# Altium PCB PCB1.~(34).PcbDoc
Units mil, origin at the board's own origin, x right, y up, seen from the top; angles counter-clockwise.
Board outline 2677.17 x 2677.17 mil, 2 copper layers (Top Layer, Bottom Layer); 27 components, 21 nets, 95 pads, 0 vias.
Unrouted connection lines stored in the file: 51.
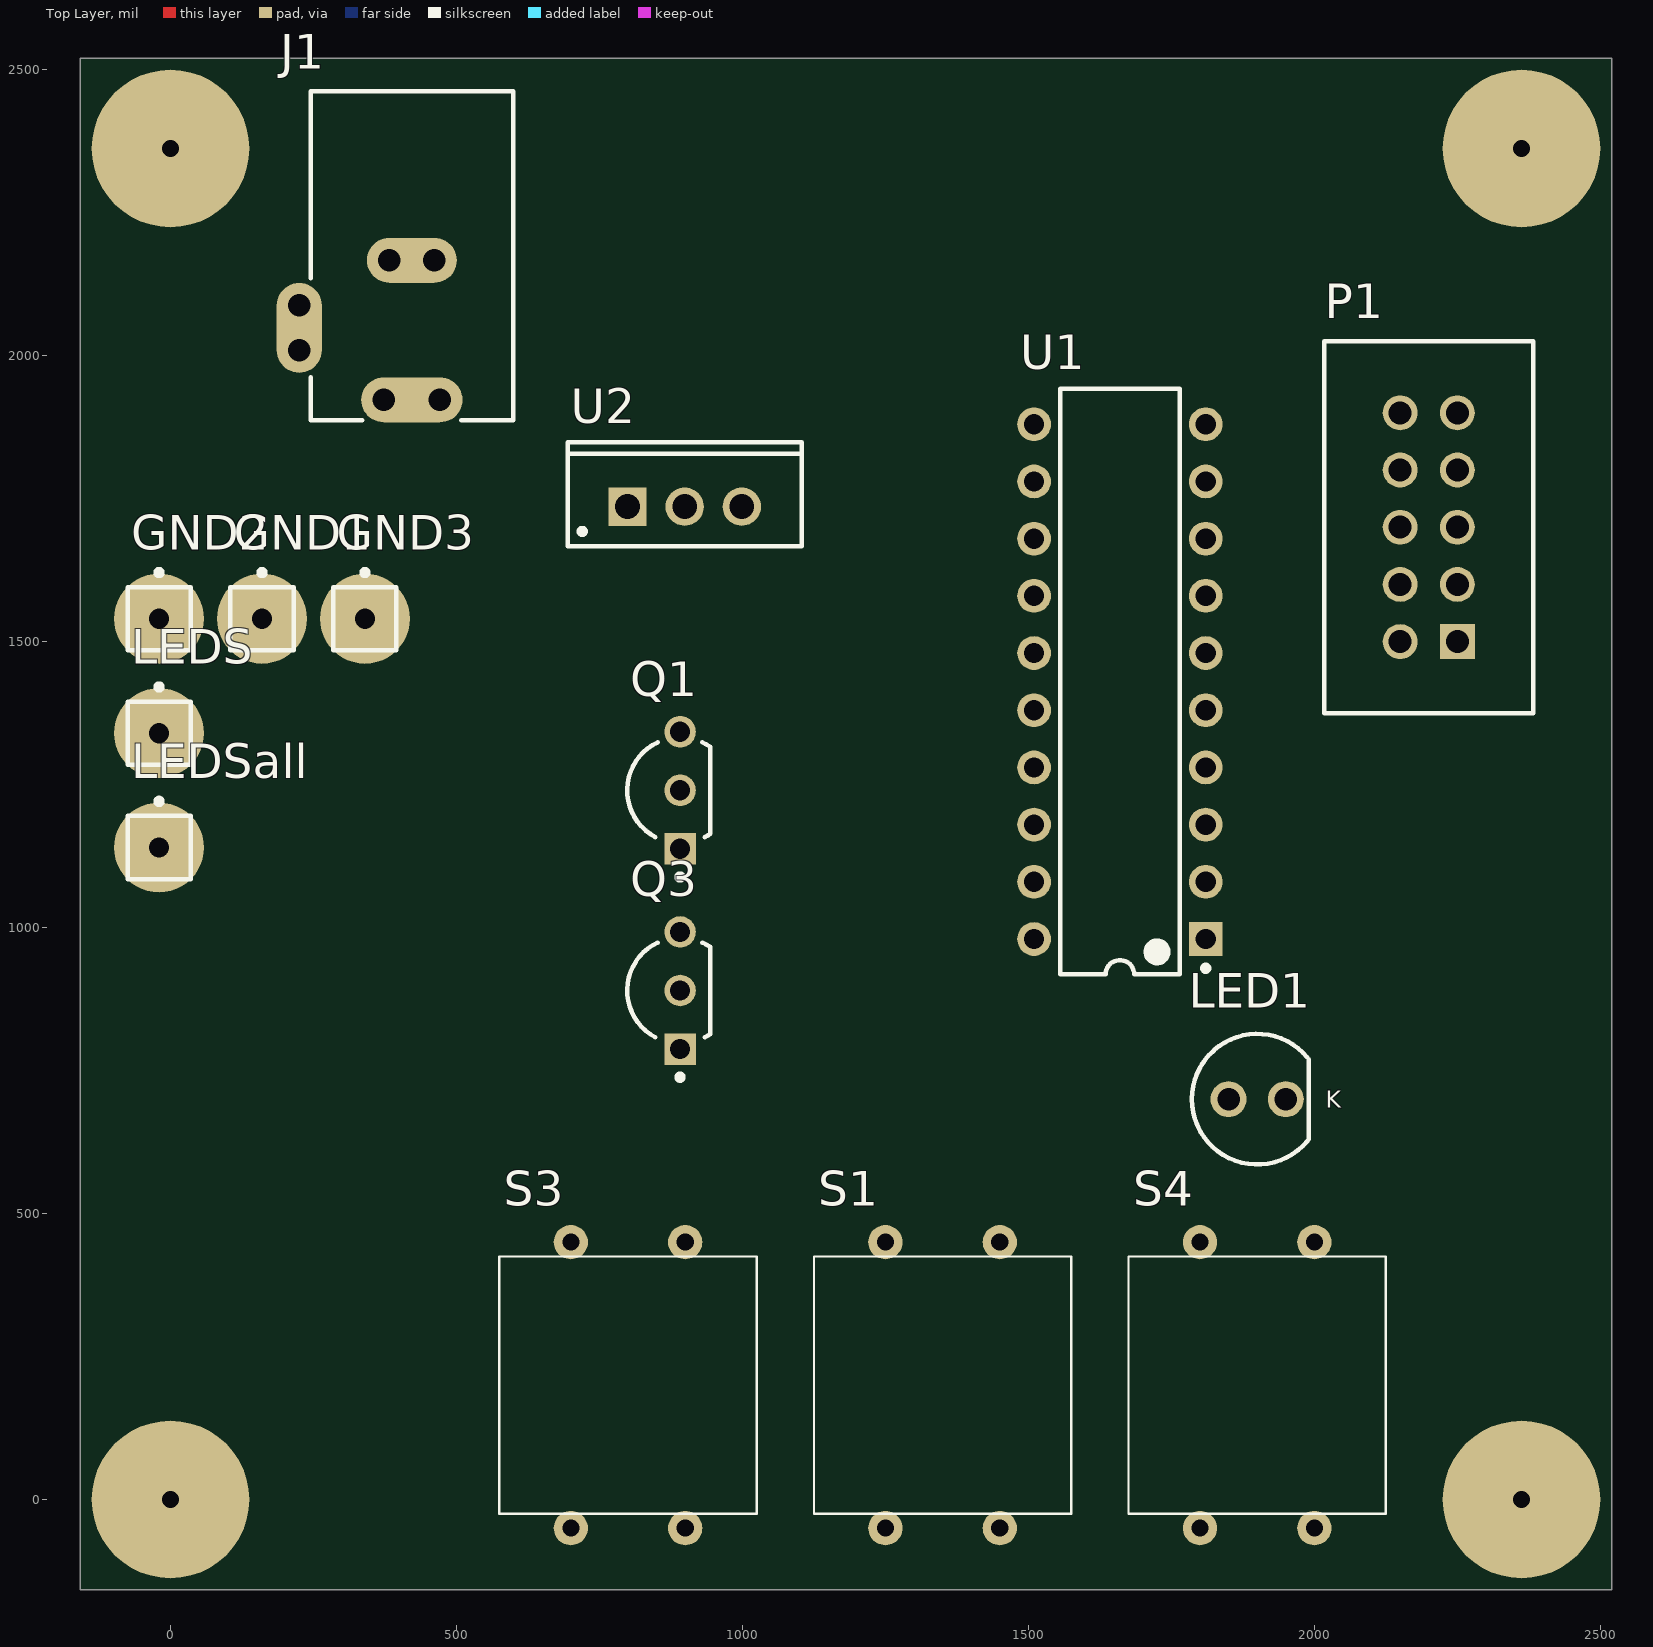
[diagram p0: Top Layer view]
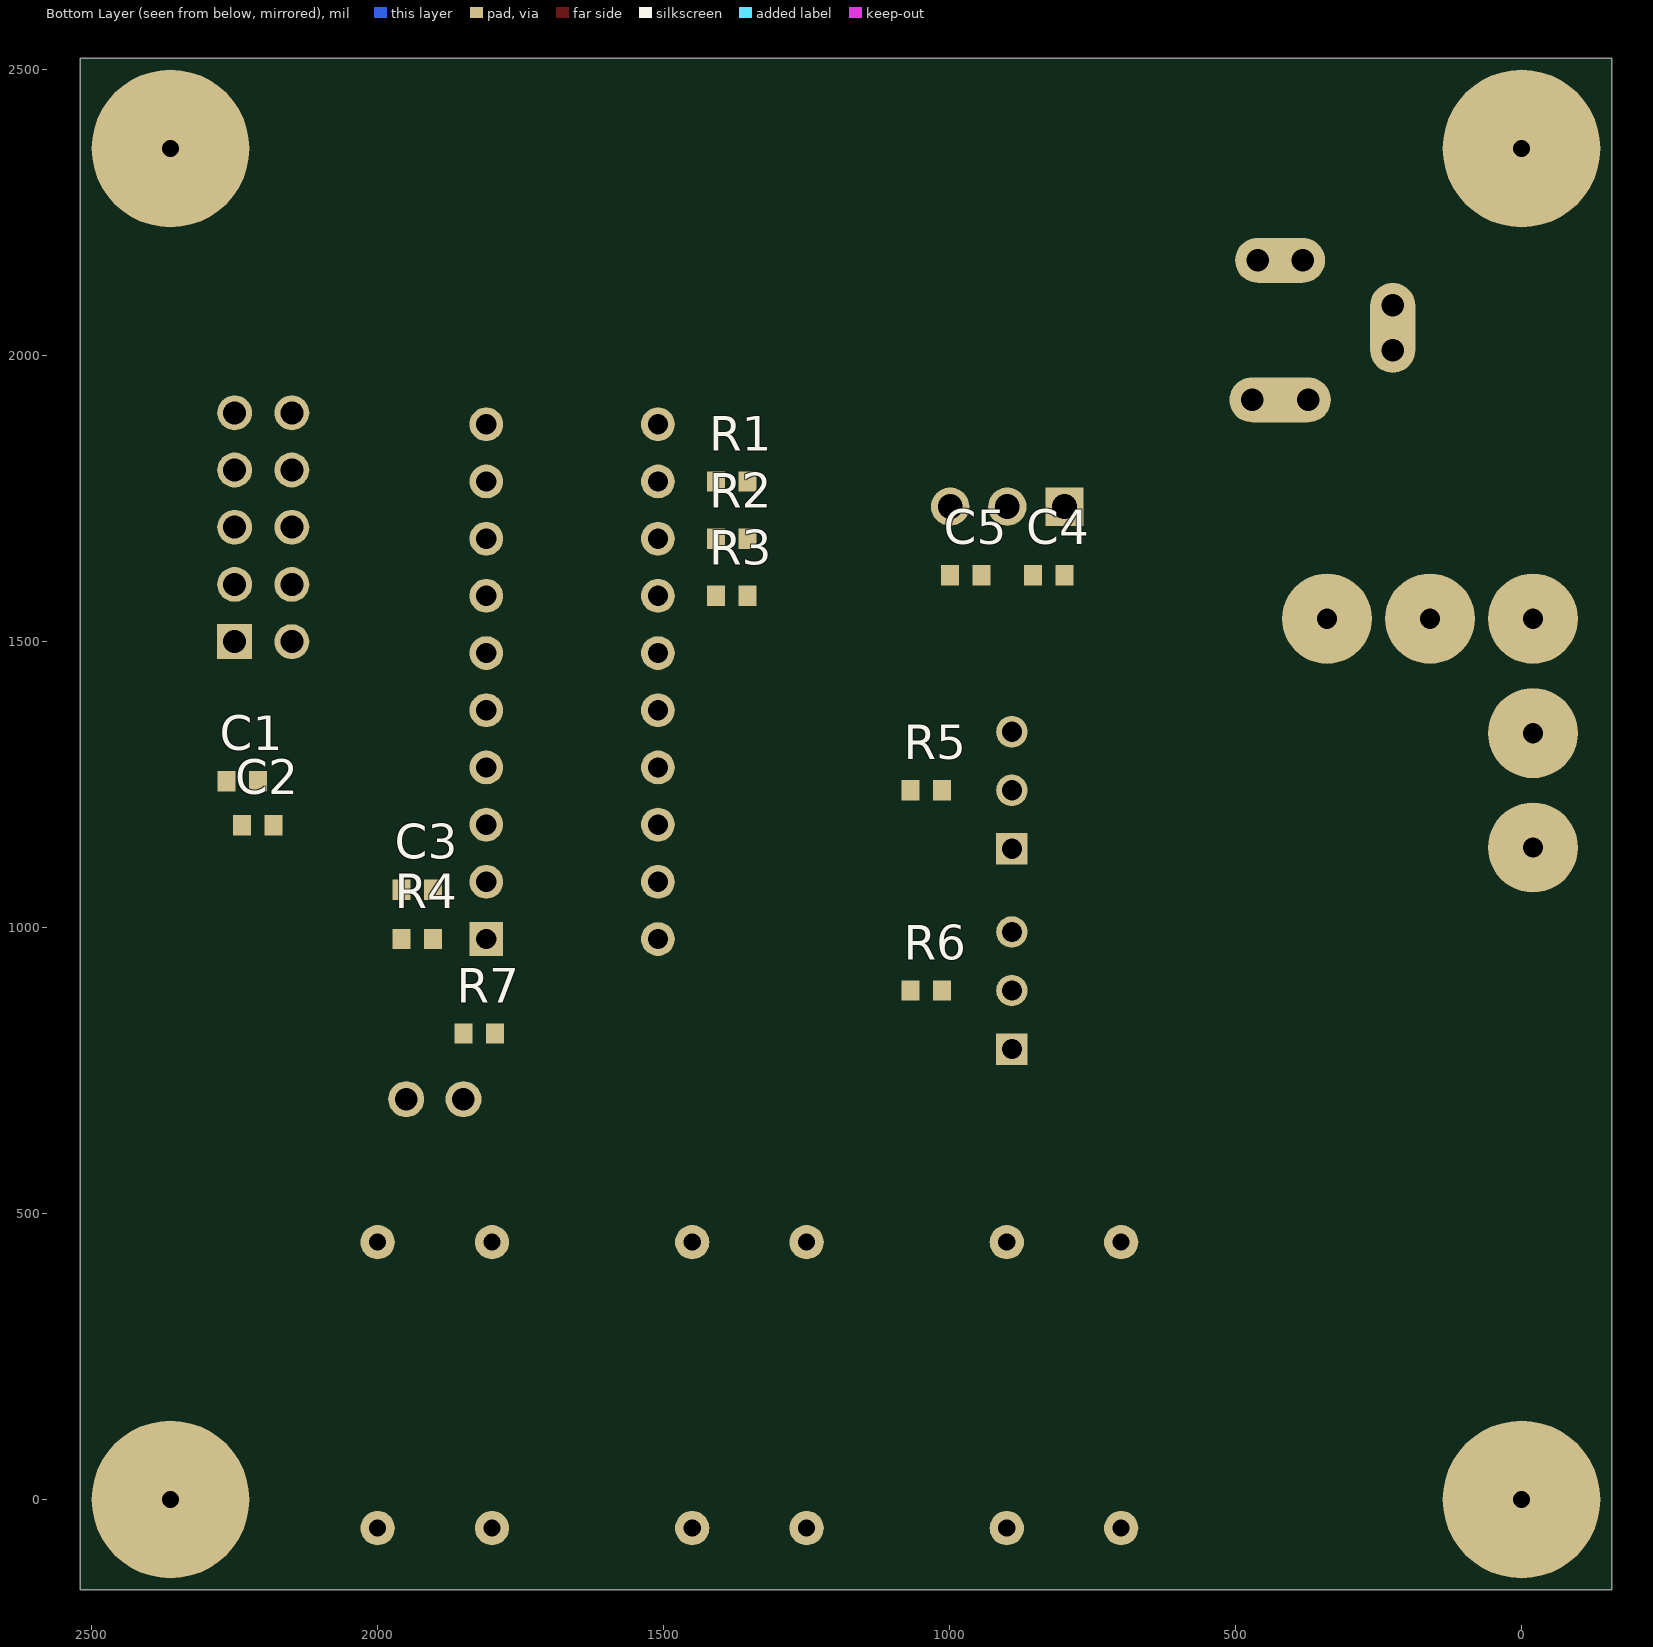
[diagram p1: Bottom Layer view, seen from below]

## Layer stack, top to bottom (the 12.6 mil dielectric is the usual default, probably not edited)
Top Solder: solder mask 0.4, Solder Resist, Dk 3.5
Top Layer: signal copper 1.4
Dielectric 1: dielectric 12.6, FR-4, Dk 4.8
Bottom Layer: signal copper 1.4
Bottom Solder: solder mask 0.4, Solder Resist, Dk 3.5

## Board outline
-157.48,-157.48 2519.68,-157.48 2519.68,2519.68 -157.48,2519.68

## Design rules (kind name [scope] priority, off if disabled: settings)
Clearance Clearance_U1_1 [InComponent('U1') vs IsRegion] p1: gap=10
Clearance Clearance_U1 [InComponent('U1') vs OnLayer('Top Layer')] p2: gap=7
Clearance [All] p3: gap=10
MinimumSolderMaskSliver [All] p1 off: minsoldermaskwidth=10
PasteMaskExpansion [All] p1 off: expansion=0
PolygonConnect [All] p1: connectstyle=Relief reliefconductorwidth=10 reliefentries=4 polygonreliefangle="90 Angle" airgapwidth=10
RoutingVias [All] p1: holewidth=28 width=50 viastyle="Through Hole" minholewidth=10 minwidth=20 maxholewidth=30 maxwidth=50
SolderMaskExpansion [All] p1 off: expansion=4
Width [All] p1: maxlimit=20 minlimit=10 preferedwidth=10
28 further rules are at their usual default settings.

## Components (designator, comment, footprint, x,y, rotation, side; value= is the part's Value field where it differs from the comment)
C1 "Cap Semi" CAPC1608L 2237,1256 r180 bottom
C2 "Cap Semi" CAPC1608L 2210,1179 r180 bottom
C3 "Cap Semi" CAPC1608L 1931,1066 r0 bottom
C4 "Cap Semi" CAPC1608L 826.56,1616 r180 bottom
C5 "Cap Semi" CAPC1608L 971.44,1616 r0 bottom
GND1 "GNDout" PIN1 160,1540 r0 top
GND2 "GNDout" PIN1 -20,1540 r0 top
GND3 "GNDout" PIN1 340,1540 r0 top
J1 "PWR2.5" PCBComponent_1 422,2162 r270 top
LED1 "151051YS04000" "Type 5mm" 1900,700 r0 top
LEDS "uleds" PIN1 -20,1340 r0 top
LEDSall "uleds_all" PIN1 -20,1140 r0 top
P1 "ZSS-105-01-F-D-450" SMTC-ZSS-105-01-X-D-450 2250,1500 r90 top
Q1 "2N5551" ONSC-TO-92-3-29-11_AM_BL 891,1240 r90 top
Q3 "2N5551" ONSC-TO-92-3-29-11_AM_BL 891,890 r90 top
R1 "Res3" CAPC1608L 1381,1780 r0 bottom
R2 "Res3" CAPC1608L 1381,1680 r0 bottom
R3 "Res3" CAPC1608L 1381,1580 r0 bottom
R4 "Res3" CAPC1608L 1931,980 r180 bottom
R5 "Res3" CAPC1608L 1041,1240 r180 bottom
R6 "Res3" CAPC1608L 1041,890 r180 bottom
R7 "Res3" CAPC1608L 1822.44,815 r0 bottom
S1 "START_min" key 1350,200 r180 top
S3 "START_all" key 800,200 r180 top
S4 "PAUSE" key 1900,200 r180 top
U1 "ATtiny2313V-10PU" 20P3 1660,1430 r180 top
U2 "MC78M05CTG" TO220 899,1736 r0 top

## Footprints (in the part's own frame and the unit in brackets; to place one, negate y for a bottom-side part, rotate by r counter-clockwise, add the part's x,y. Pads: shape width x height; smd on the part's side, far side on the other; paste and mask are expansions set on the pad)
20P3 [mm] "DIP, 20-Pin, Row Spacing 7.62 mm, Pitch 2.54 mm"
  rect 1.5x1.5 hole 0.9: 1(-3.81,11.43)
  round 1.5 hole 0.9: 2(-3.81,8.89) 3(-3.81,6.35) 4(-3.81,3.81) 5(-3.81,1.27) 6(-3.81,-1.27) 7(-3.81,-3.81) 8(-3.81,-6.35) 9(-3.81,-8.89) 10(-3.81,-11.43) 11(3.81,-11.43) 12(3.81,-8.89) 13(3.81,-6.35) 14(3.81,-3.81) 15(3.81,-1.27) 16(3.81,1.27) 17(3.81,3.81) 18(3.81,6.35) 19(3.81,8.89) 20(3.81,11.43)
  silkscreen extent -3.94,-13 2.65,13, body extent -3.6,-12.95 3.6,12.95, height 5.08
CAPC1608L [mm] "Chip Capacitor, Body 1.6x0.8mm, IPC High Density"
  rect 0.8x0.9 smd: 1(-0.7,0) 2(0.7,0)
  body extent -0.87,-0.48 0.87,0.48, height 1.3
key [mil]
  round 60 hole 30: 1(100,-250) 2(-100,-250) 3(-100,250) 4(100,250)
  silkscreen extent -225,-225 225,225, body extent -250,-250 250,250, height 470
ONSC-TO-92-3-29-11_AM_BL [mm] "TO, 3-Leads, Body Dia 4.7mm, Pitch 2.6mm"
  rect 1.4x1.4 hole 0.9: 1(-2.6,0)
  round 1.4 hole 0.9: 2(0,0) 3(2.6,0)
  silkscreen extent -3.97,-1.34 2.13,2.35, body extent -2.84,-1.34 2.84,2.35, height 5.33
PCBComponent_1 [mm]
  oval 2x4.5 all layers, no hole: 1(6.08,0)
  round 1.5 hole 1: 1A(6.08,-1.25) 1B(6.08,1.25) 2A(-0.12,-1) 2B(-0.12,1) 3A(1.88,-5) 3B(3.88,-5)
  oval 2x4 all layers, no hole: 2(-0.12,0)
  oval 4x2 all layers, no hole: 3(2.88,-5)
  silkscreen extent -7.62,-4.5 6.98,4.5, body extent -7.87,-5.6 6.83,5.6, height 11
PIN1 [mm] "Connector; Plug"
  round 4 hole 0.9: 1(0,0)
  silkscreen extent -1.4,-1.4 1.4,2.17
SMTC-ZSS-105-01-X-D-450 [mm] "Shrouded .025\" SQ Post Header, 2x5 Pins, Vertical, 2.54mm Pitch, Male"
  rect 1.55x1.55 hole 1.02: 1(0,0)
  round 1.55 hole 1.02: 2(0,2.54) 3(2.54,0) 4(2.54,2.54) 5(5.08,0) 6(5.08,2.54) 7(7.62,0) 8(7.62,2.54) 9(10.16,0) 10(10.16,2.54)
  silkscreen extent -3.18,-3.36 13.33,5.9, body extent -3.17,-3.57 13.34,5.91, height 11.43
TO220 [mm] "TO, Thru-Hole, Vertical, Heatsink Mounted; 3 In-Line Leads; Pitch 2.54 mm"
  rect 1.7x1.7 hole 1.1: 1(-2.54,0)
  round 1.7 hole 1.1: 2(0,0) 3(2.54,0)
  silkscreen extent -5.2,-1.75 5.2,2.85, body extent -5.25,-1.8 5.25,2.9, height 19.7
"Type 5mm" [mm] "THT, LED-5mm, 2pin- Body 5.8mm"
  round 1.6 hole 1: 1(1.27,0) 2(-1.27,0)
  silkscreen extent -2.9,-2.9 2.29,2.9, body extent -2.9,-2.9 2.5,2.9, height 11.7

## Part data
C1 C2 C3 C4 C5: "Capacitor (Semiconductor SIM Model)"
GND1 GND2 GND3 LEDS LEDSall: library part Plug, "Plug"
J1: "Low Voltage Power Supply Connector"
LED1: library part CMP-1488-00010-1, "THT LED round mono-color color lens, WL-TMRW, Yellow"
P1: library part CMP-1024-00461-1
Q1 Q3: library part CMP-1048-01479-1, "Amplifier Transistor, NPN Silicon, 3-Pin TO-92, Pb-Free, Tape and Reel"
R1 R2 R3 R4 R5 R6 R7: "Resistor"
S1 S3 S4: library part SW-DPST, "Double-Pole, Single-Throw Switch"
U1: library part CMP-0093-00017-1, "Low Power tinyAVR® 8-Bit Microcontroller, 2K Flash Memory, 10MHz, Industrial Temperature, 20-Lead PDIP, Pb-Free"
U2: library part CMP-0244-00483-1, "Positive Voltage Regulator, 5V, 3-Pin TO-220"

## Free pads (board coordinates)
  round 275.59 hole 30: 4(0,0) 5(2362.2,0) 7(2362.2,2362.2) 8(0,2362.2)

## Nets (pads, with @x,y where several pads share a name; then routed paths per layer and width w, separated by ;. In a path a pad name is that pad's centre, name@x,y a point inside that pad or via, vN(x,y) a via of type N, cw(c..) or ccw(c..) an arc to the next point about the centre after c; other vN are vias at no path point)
+24V: C4.2 J1.1 J1.1A J1.1B Q1.3 Q3.3 U2.1
BUT_PAUSE: R3.2 S4.1 U1.14
BUT_START: R1.2 S1.1 U1.12
BUT_STARTALL: R2.2 S3.1 U1.13
GND: C1.1 C2.1 C3.2 C4.1 C5.1 GND1.1 GND2.1 GND3.1 J1.3 J1.3A J1.3B LED1.1 P1.4 P1.6 P1.8 P1.10 S1.2 S3.2 S4.2 U1.10 U2.2
MISO: P1.9 U1.18
MOSI: P1.1 U1.17
NetC1_2: C1.2 U1.4
NetC2_2: C2.2 U1.5
NetJ1_2: J1.2 J1.2A J1.2B
NetLED1_2: LED1.2 R7.2
NetLEDS_1: LEDS.1 Q1.1
NetLEDSall_1: LEDSall.1 Q3.1
NetQ1_2: Q1.2 R5.2
NetQ3_2: Q3.2 R6.2
NetR7_1: R7.1 U1.11
RES: C3.1 P1.5 R4.2 U1.1
SCK: P1.7 U1.19
ULEDS: R5.1 U1.15
ULEDSALL: R6.1 U1.16
VCC: C5.2 P1.2 R1.1 R2.1 R3.1 R4.1 U1.20 U2.3
pads on no net: P1.3 S1.3 S1.4 S3.3 S3.4 S4.3 S4.4 U1.2 U1.3 U1.6 U1.7 U1.8 U1.9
